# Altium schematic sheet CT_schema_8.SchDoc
size 277 x 170 mm
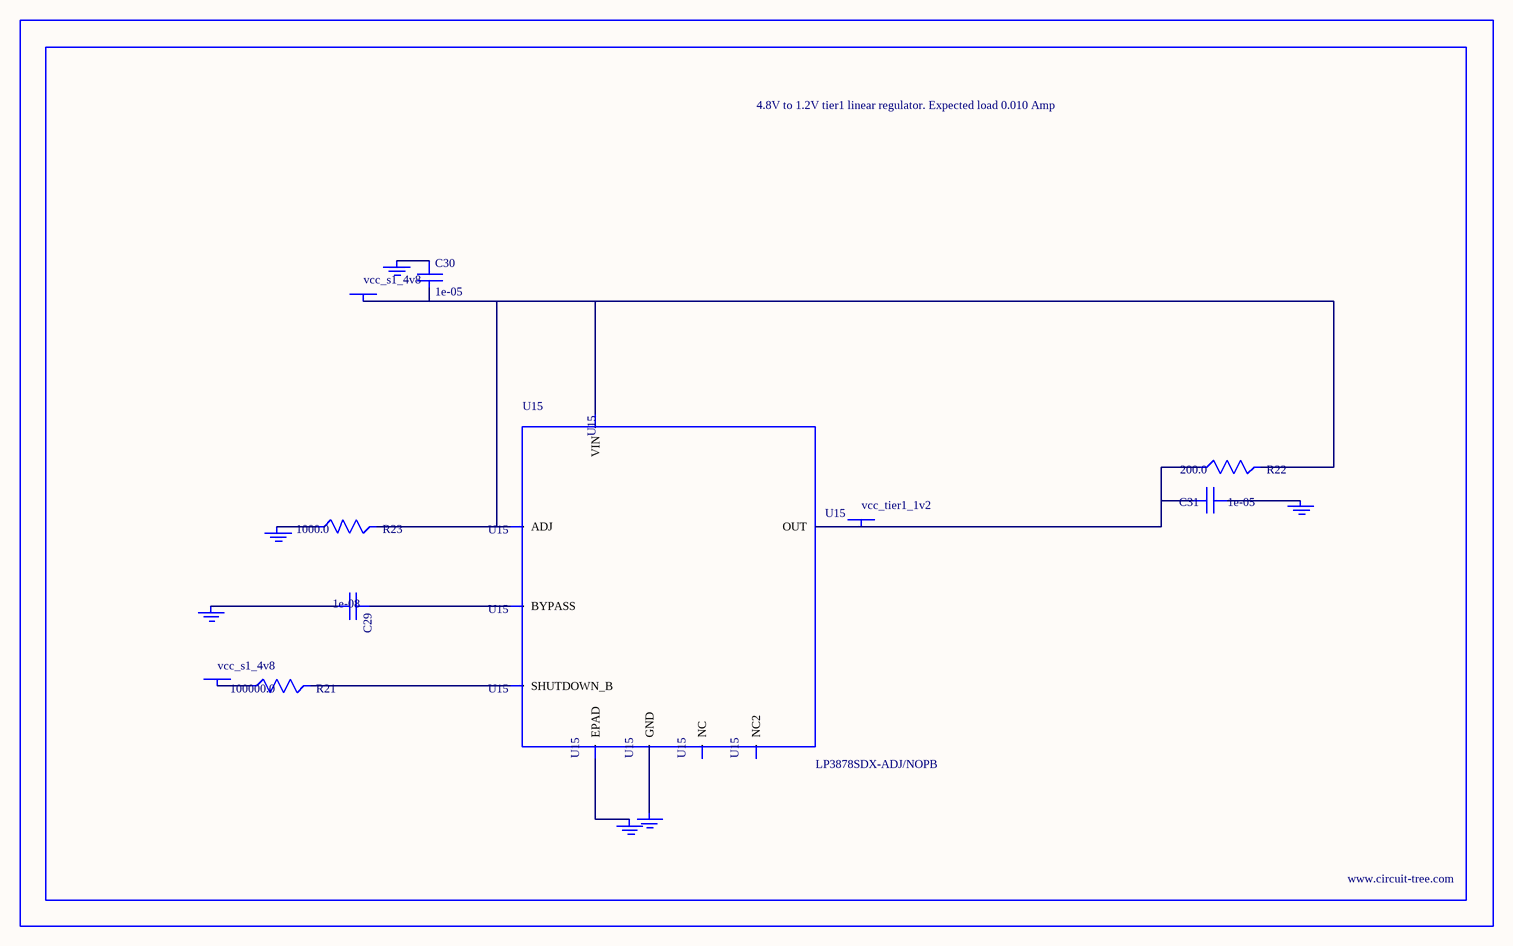
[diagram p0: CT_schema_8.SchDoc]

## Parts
BORDER7  (no value)
C29  1e-08  [C0402]
C30  1e-05  [C1206]
C31  1e-05  [C0805]
GND_INSTANCE_7_0  (no value)
GND_INSTANCE_7_1  (no value)
GND_INSTANCE_7_2  (no value)
GND_INSTANCE_7_3  (no value)
GND_INSTANCE_7_4  (no value)
GND_INSTANCE_7_5  (no value)
POWER_INSTANCE_7_0  vcc_s1_4v8
POWER_INSTANCE_7_1  vcc_s1_4v8
POWER_INSTANCE_7_2  vcc_tier1_1v2
R21  100000.0  [R0603]
R22  200.0  [R0603]
R23  1000.0  [R0603]
U15  LP3878SDX-ADJ/NOPB  [WSON-8]

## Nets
NetC29_1: C29.1 U15.1(BYPASS)
NetC29_2: C29.2 GND_INSTANCE_7_0.0(GND)
NetC30_1: C30.1 GND_INSTANCE_7_1.0(GND)
NetC30_2: C30.2 POWER_INSTANCE_7_0.0(PWR) R22.2 R23.2 U15.4(VIN) U15.6(ADJ)
NetC31_1: C31.1 GND_INSTANCE_7_2.0(GND)
NetC31_2: C31.2 POWER_INSTANCE_7_2.0(PWR) R22.1 U15.5(OUT)
NetGND_INSTANCE_7_3_0: GND_INSTANCE_7_3.0(GND) R23.1
NetGND_INSTANCE_7_4_0: GND_INSTANCE_7_4.0(GND) U15.PAD(EPAD)
NetGND_INSTANCE_7_5_0: GND_INSTANCE_7_5.0(GND) U15.3(GND)
NetPOWER_INSTANCE_7_1_0: POWER_INSTANCE_7_1.0(PWR) R21.1
NetR21_2: R21.2 U15.8(SHUTDOWN_B)

Not connected (* = marked no-connect by the designer): U15 2(NC) 7(NC2)

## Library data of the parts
BORDER7 = BORDER_PAGE7
C29 = C0402C103K3RAC
C30 = C1206C106K3RACTU
C31 = GRM219R60J106ME19D
GND_INSTANCE_7_0-GND_INSTANCE_7_5 = GND
POWER_INSTANCE_7_0-POWER_INSTANCE_7_2 = PWR
R21 = RC0603JR-07100KL
R22 = RC0603JR-07200RL
R23 = RC0603JR-071KL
